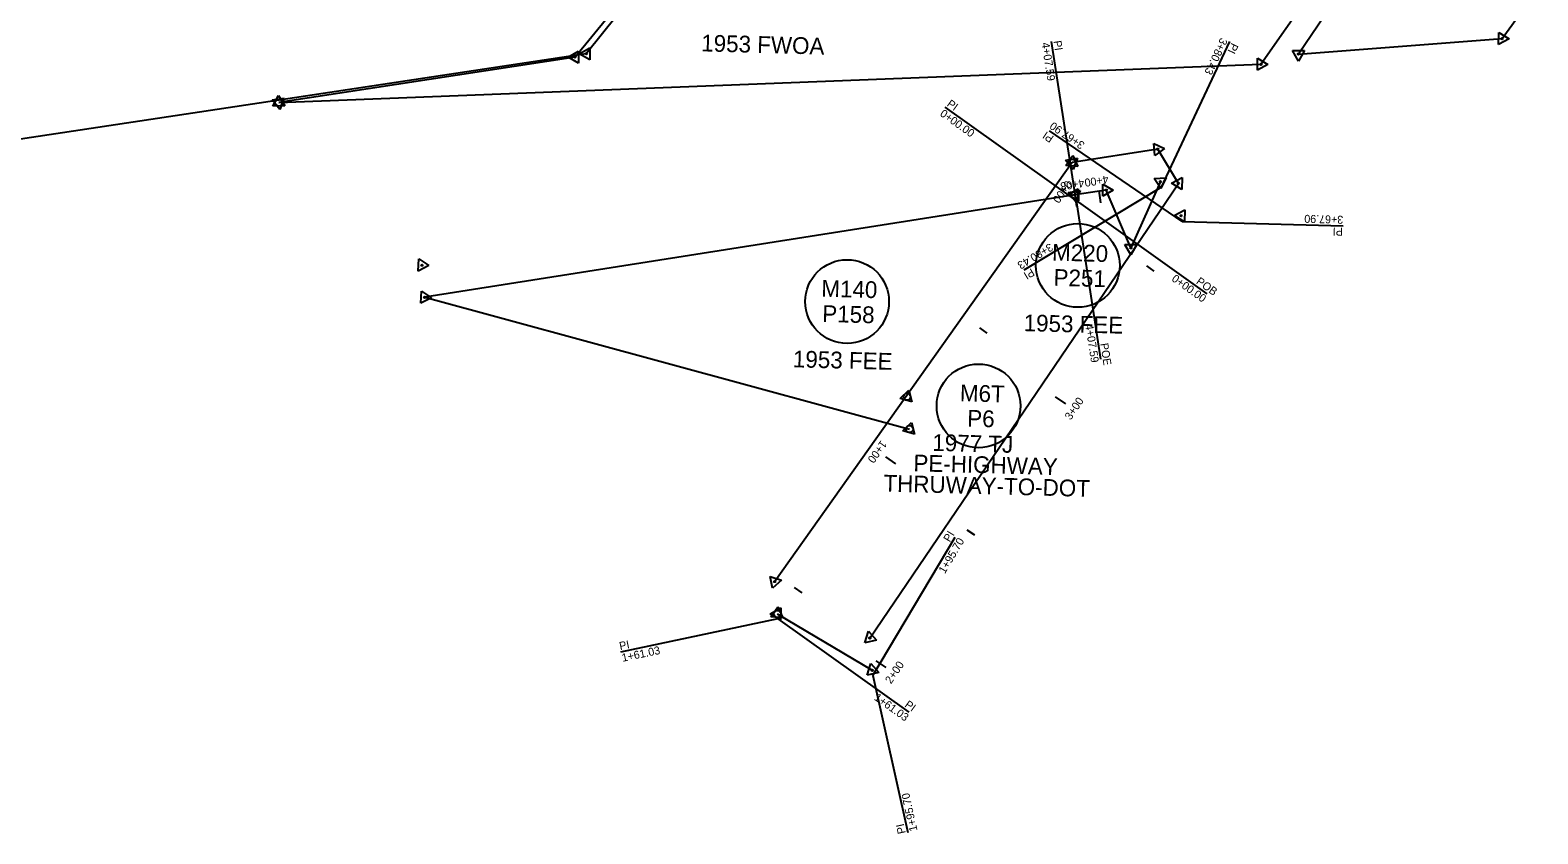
# Model space of a CAD drawing. Extents: x 325029 to 414988, y 1517527 to 1550420.
# Drawn here: x 359632.1 to 360104.7, y 1524381.8 to 1524633.6 of the extents above; entities that cross this region are included whole.
import ezdxf

# ---------------------------------------------------------------- set-up
doc = ezdxf.new("R2010")
doc.units = 0
for name, color, linetype in [('ACSC_P_T', 7, 'Continuous'), ('ACSCT_P', 7, 'Continuous'), ('ACSR_P_T', 7, 'Continuous'), ('ACSRT_P', 7, 'Continuous'), ('Level 56', 7, 'Continuous'), ('MEE', 7, 'Continuous'), ('MHB', 7, 'Continuous'), ('MHBWOA', 7, 'Continuous'), ('XDEFAULT_P', 7, 'Continuous')]:
    doc.layers.add(name, color=color, linetype=linetype)

msp = doc.modelspace()

# ---------------------------------------------------------------- linework, layer by layer
at = {"layer": 'ACSCT_P'}
for points in [[(359959.98, 1524580.27), (359952.25, 1524630.07)], [(359986.82, 1524584.43), (360008.16, 1524630.09)], [(359959.98, 1524580.27), (359918.93, 1524609.51)], [(359993.29, 1524573.7), (359951.64, 1524602.07)], [(359986.82, 1524584.43), (359943.66, 1524558.41)], [(359959.98, 1524580.27), (360001.03, 1524551.03)], [(359959.98, 1524580.27), (359967.7, 1524530.46)], [(359993.29, 1524573.7), (360043.67, 1524572.3)], [(359896.34, 1524431.38), (359922.12, 1524474.69)], [(359866.55, 1524449.11), (359817.23, 1524438.73)], [(359866.55, 1524449.11), (359907.6, 1524419.87)], [(359896.34, 1524431.38), (359907.25, 1524382.17)]]:
    msp.add_lwpolyline(points, dxfattribs=at)
at = {"layer": 'ACSRT_P'}
for points in [[(359961.54, 1524579.15), (359958.41, 1524581.38)], [(359960.27, 1524578.37), (359959.68, 1524582.16)], [(359960.27, 1524578.37), (359959.68, 1524582.16)], [(359967.77, 1524579.53), (359967.19, 1524583.33)], [(359982.02, 1524559.72), (359984.4, 1524558.1)], [(359932.14, 1524538.71), (359929.79, 1524540.38)], [(359953.48, 1524518.66), (359956.65, 1524516.5)], [(359903.52, 1524497.7), (359900.39, 1524499.93)], [(359925.73, 1524477.07), (359928.11, 1524475.45)], [(359874.12, 1524457.26), (359871.78, 1524458.93)], [(359897.18, 1524436.02), (359900.35, 1524433.86)]]:
    msp.add_lwpolyline(points, dxfattribs=at)
at = {"layer": 'Level 56'}
for centre in [(359960.54, 1524559.88), (359888.22, 1524548.55), (359929.42, 1524515.86)]:
    msp.add_circle(centre, 13.12, dxfattribs=at)
at = {"layer": 'MEE'}
for p, q in [((359986.43, 1524586.16), (359977.17, 1524565.38)), ((359969.47, 1524583.48), (359959.58, 1524581.97)), ((359977.17, 1524565.38), (359969.47, 1524583.48)), ((359866.31, 1524450.7), (359896.13, 1524433.01))]:
    msp.add_line(p, q, dxfattribs=at)
for points in [[(359984.47, 1524587.13), (359988.24, 1524587.37)], [(359986.56, 1524583.99), (359984.47, 1524587.13)], [(359988.24, 1524587.37), (359986.56, 1524583.99)], [(359957.4, 1524581.91), (359960.62, 1524583.89)], [(359960.73, 1524580.11), (359957.4, 1524581.91)], [(359960.62, 1524583.89), (359960.73, 1524580.11)], [(359968.41, 1524581.58), (359968.35, 1524585.36)], [(359968.35, 1524585.36), (359971.65, 1524583.52)], [(359971.65, 1524583.52), (359968.41, 1524581.58)], [(359990.73, 1524575.5), (359994.05, 1524577.3)], [(359994.05, 1524577.3), (359993.95, 1524573.52)], [(359993.95, 1524573.52), (359990.73, 1524575.5)], [(359977.15, 1524563.2), (359975.29, 1524566.49)], [(359975.29, 1524566.49), (359979.07, 1524566.46)], [(359979.07, 1524566.46), (359977.15, 1524563.2)], [(359864.13, 1524450.73), (359867.43, 1524452.57)], [(359867.38, 1524448.8), (359864.13, 1524450.73)], [(359864.33, 1524449.79), (359866.52, 1524452.88)], [(359868.09, 1524449.44), (359864.33, 1524449.79)], [(359866.52, 1524452.88), (359868.09, 1524449.44)], [(359867.43, 1524452.57), (359867.38, 1524448.8)], [(359894.52, 1524431.53), (359895.65, 1524435.13)], [(359895.65, 1524435.13), (359898.21, 1524432.35)], [(359898.21, 1524432.35), (359894.52, 1524431.53)]]:
    msp.add_lwpolyline(points, dxfattribs=at)
for centre, radius in [((359986.43, 1524586.16), 0.227), ((359959.58, 1524581.97), 0.227), ((359969.47, 1524583.48), 0.227), ((359992.91, 1524575.44), 0.227), ((359977.17, 1524565.38), 0.227), ((359866.31, 1524450.7), 1.09), ((359866.32, 1524450.7), 1.09), ((359896.13, 1524433.01), 0.227)]:
    msp.add_circle(centre, radius, dxfattribs=at)
at = {"layer": 'MHB'}
for p, q in [((359959.58, 1524581.97), (359755.81, 1524549.9)), ((359755.81, 1524549.9), (359907.79, 1524508.6))]:
    msp.add_line(p, q, dxfattribs=at)
for points in [[(359957.55, 1524582.75), (359961.28, 1524583.34)], [(359959.92, 1524579.82), (359957.55, 1524582.75)], [(359961.28, 1524583.34), (359959.92, 1524579.82)], [(359754.61, 1524548.07), (359754.82, 1524551.85)], [(359757.98, 1524549.78), (359754.61, 1524548.07)], [(359754.82, 1524551.85), (359757.98, 1524549.78)], [(359905.68, 1524508.04), (359908.36, 1524510.7)], [(359908.36, 1524510.7), (359909.32, 1524507.05)], [(359909.32, 1524507.05), (359905.68, 1524508.04)]]:
    msp.add_lwpolyline(points, dxfattribs=at)
for centre, radius in [((359959.58, 1524581.97), 1.09), ((359755.81, 1524549.9), 0.227), ((359907.79, 1524508.6), 1.09)]:
    msp.add_circle(centre, radius, dxfattribs=at)
at = {"layer": 'MHBWOA'}
for p, q in [((360093.54, 1524630.95), (360281.17, 1524891.53)), ((359881.4, 1524719.64), (359806.47, 1524626.22)), ((359871.28, 1524708.7), (359802.97, 1524625.17)), ((360056.94, 1524666.37), (360029.7, 1524626.12)), ((360017.95, 1524622.91), (360045.37, 1524662.31)), ((360029.7, 1524626.12), (360093.54, 1524630.95)), ((359806.47, 1524626.22), (359590.71, 1524593.62)), ((359802.97, 1524625.17), (359710.06, 1524610.93)), ((359710.06, 1524610.93), (360017.95, 1524622.91))]:
    msp.add_line(p, q, dxfattribs=at)
for points in [[(360092.43, 1524629.08), (360092.48, 1524632.85)], [(360092.48, 1524632.85), (360095.73, 1524630.92)], [(359804.29, 1524626.23), (359807.56, 1524628.11)], [(359807.56, 1524628.11), (359807.56, 1524624.33)], [(360095.73, 1524630.92), (360092.43, 1524629.08)], [(359800.79, 1524625.18), (359804.07, 1524627.05)], [(359804.05, 1524623.28), (359800.79, 1524625.18)], [(359804.07, 1524627.05), (359804.05, 1524623.28)], [(359807.56, 1524624.33), (359804.29, 1524626.23)], [(360016.82, 1524621.04), (360016.9, 1524624.82)], [(360016.9, 1524624.82), (360020.13, 1524622.86)], [(360027.8, 1524627.2), (360031.58, 1524627.21)], [(360029.7, 1524623.94), (360027.8, 1524627.2)], [(360031.58, 1524627.21), (360029.7, 1524623.94)], [(360020.13, 1524622.86), (360016.82, 1524621.04)], [(359708.02, 1524611.73), (359711.76, 1524612.3)], [(359710.38, 1524608.78), (359708.02, 1524611.73)], [(359708.21, 1524609.76), (359709.97, 1524613.11)], [(359711.99, 1524609.91), (359708.21, 1524609.76)], [(359709.97, 1524613.11), (359711.99, 1524609.91)], [(359711.76, 1524612.3), (359710.38, 1524608.78)]]:
    msp.add_lwpolyline(points, dxfattribs=at)
for centre, radius in [((360093.54, 1524630.95), 0.227), ((359802.97, 1524625.17), 0.227), ((359806.47, 1524626.22), 0.227), ((360029.7, 1524626.12), 0.227), ((360017.95, 1524622.91), 0.227), ((359710.06, 1524610.93), 1.09), ((359710.05, 1524610.93), 1.09)]:
    msp.add_circle(centre, radius, dxfattribs=at)
at = {"layer": 'XDEFAULT_P'}
for p, q in [((359985.59, 1524596.32), (359958.75, 1524592.11)), ((359992.07, 1524585.6), (359985.59, 1524596.32)), ((359958.75, 1524592.11), (359865.53, 1524460.81)), ((359895.35, 1524443.13), (359992.07, 1524585.6))]:
    msp.add_line(p, q, dxfattribs=at)
for points in [[(359984.67, 1524594.34), (359984.34, 1524598.11)], [(359984.34, 1524598.11), (359987.76, 1524596.51)], [(359987.76, 1524596.51), (359984.67, 1524594.34)], [(359956.71, 1524592.9), (359960.44, 1524593.49)], [(359956.71, 1524592.9), (359960.45, 1524593.49)], [(359959.09, 1524589.96), (359956.71, 1524592.9)], [(359959.09, 1524589.96), (359956.71, 1524592.9)], [(359956.76, 1524591.21), (359958.95, 1524594.29)], [(359960.52, 1524590.85), (359956.76, 1524591.21)], [(359958.95, 1524594.29), (359960.52, 1524590.85)], [(359960.44, 1524593.49), (359959.09, 1524589.96)], [(359960.45, 1524593.49), (359959.09, 1524589.96)], [(359989.9, 1524585.65), (359993.22, 1524587.46)], [(359993.12, 1524583.68), (359989.9, 1524585.65)], [(359993.22, 1524587.46), (359993.12, 1524583.68)], [(359753.79, 1524558.13), (359753.99, 1524561.91)], [(359753.99, 1524561.91), (359757.16, 1524559.84)], [(359757.16, 1524559.84), (359753.79, 1524558.13)], [(359904.87, 1524518.16), (359907.55, 1524520.82)], [(359907.55, 1524520.82), (359908.52, 1524517.17)], [(359908.52, 1524517.17), (359904.87, 1524518.16)], [(359864.07, 1524462.43), (359867.66, 1524461.26)], [(359864.85, 1524458.73), (359864.07, 1524462.43)], [(359867.66, 1524461.26), (359864.85, 1524458.73)], [(359893.75, 1524441.65), (359894.88, 1524445.25)], [(359894.88, 1524445.25), (359897.43, 1524442.47)], [(359897.43, 1524442.47), (359893.75, 1524441.65)]]:
    msp.add_lwpolyline(points, dxfattribs=at)
for centre, radius in [((359985.59, 1524596.32), 0.227), ((359958.75, 1524592.11), 1.09), ((359958.75, 1524592.11), 1.09), ((359958.75, 1524592.11), 1.09), ((359992.07, 1524585.6), 0.227), ((359754.98, 1524559.96), 0.227), ((359906.98, 1524518.72), 1.09), ((359865.53, 1524460.81), 0.227), ((359895.35, 1524443.13), 0.227)]:
    msp.add_circle(centre, radius, dxfattribs=at)

# ---------------------------------------------------------------- texts
at = {"layer": 'ACSC_P_T'}
for s, rotation, p in [('4+07.59', 278.8149, (359949.16, 1524629.59)), ('PI', 278.8149, (359952.87, 1524630.17)), ('3+80.43', 244.95, (360005.33, 1524631.41)), ('PI', 244.95, (360008.73, 1524629.82)), ('PI', 324.5373, (359919.29, 1524610.02)), ('0+00.00', 324.5373, (359917.11, 1524606.96)), ('3+67.90', 145.7379, (359962.92, 1524598.17)), ('PI', 145.7379, (359953.22, 1524600.24)), ('3+67.90', 178.4115, (360043.76, 1524575.43)), ('PI', 178.4115, (360043.65, 1524571.68)), ('3+80.43', 211.0852, (359951.79, 1524566.96)), ('PI', 211.0852, (359945.99, 1524559.08)), ('0+00.00', 324.5373, (359989.73, 1524555.23)), ('POB', 324.5373, (359997.41, 1524554.37)), ('4+07.59', 278.8149, (359962.85, 1524541.32)), ('POE', 278.8149, (359967.57, 1524535.37)), ('1+95.70', 59.243, (359918.86, 1524463.1)), ('PI', 59.243, (359920.38, 1524473)), ('PI', 11.8901, (359817.1, 1524439.34)), ('1+61.03', 11.8901, (359817.88, 1524435.67)), ('1+61.03', 324.5373, (359896.49, 1524423.95)), ('PI', 324.5373, (359906.06, 1524421.74)), ('1+95.70', 102.4904, (359910.3, 1524382.85)), ('PI', 102.4904, (359906.63, 1524382.04))]:
    msp.add_text(s, height=2.501, rotation=rotation, dxfattribs=at).set_placement(p)
at = {"layer": 'ACSR_P_T'}
for s, rotation, p in [('0+00', 234.5373, (359956.9, 1524586.71)), ('4+08', 188.8149, (359962.36, 1524586.96)), ('4+08', 188.8149, (359962.36, 1524586.96)), ('4+00', 188.8149, (359969.94, 1524588.13)), ('3+00', 55.7379, (359958.3, 1524511.24)), ('1+00', 234.5373, (359898.88, 1524505.26)), ('2+00', 55.7379, (359901.98, 1524428.56))]:
    msp.add_text(s, height=2.501, rotation=rotation, dxfattribs=at).set_placement(p)
at = {"layer": 'Level 56'}
for s, height, p in [('1953 FWOA', 5.249, (359842.44, 1524626.98)), ('M220', 5.249, (359952.42, 1524561.41)), ('P251', 5.249, (359952.89, 1524553.52)), ('M140', 5.249, (359880.09, 1524550.08)), ('P158', 5.249, (359880.39, 1524542.19)), ('1953 FEE', 5.249, (359943.51, 1524539.31)), ('1953 FEE', 5.249, (359871.18, 1524527.98)), ('M6T', 5.249, (359923.53, 1524517.33)), ('P6', 5.249, (359925.82, 1524509.39)), ('1977 TJ', 5.249, (359914.88, 1524501.8)), ('PE-HIGHWAY', 5.249, (359908.96, 1524495.38)), ('THRUWAY-TO-DOT', 5.2493, (359899.56, 1524489.05))]:
    msp.add_text(s, height=height, rotation=358.4907, dxfattribs=at).set_placement(p)

doc.saveas('drawing.dxf')
